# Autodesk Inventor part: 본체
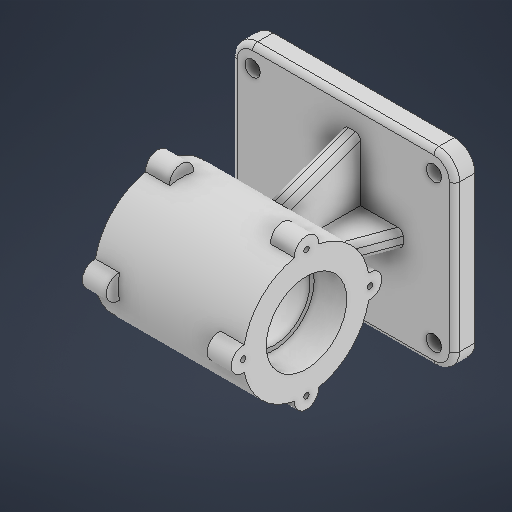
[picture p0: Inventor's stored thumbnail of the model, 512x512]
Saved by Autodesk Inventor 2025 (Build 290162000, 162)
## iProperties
Created: 2025-08
Part Number: 본체
Material: 일반
Document SubType Name: Modeling
Designer: infra11
Density: 1 g/cm^3
Appearance: 기본값
Author: infra11
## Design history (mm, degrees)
sketch "스케치1"
  geometry: L1 (-65, -55)-(65, -55); L2 (65, -55)-(65, 55); L3 (65, 55)-(-65, 55); L4 (-65, 55)-(-65, -55); L5 (-65, -55)-(65, 55); L6 (65, -55)-(-65, 55); 1 further point
  constraints: 12 end point, 2 midpoint, 2 parallel, 1 horizontal, 1 perpendicular
  dimensions: "d0" = 130 distance of L2.end L3.end; "d1" = 110 distance of L1.end L2.end
extrude "돌출1" new body sketch "스케치1" stored distance "d2" = 12; taper "d3" = 0 deg
sketch "스케치2"
  geometry: L1 (-53, -43)-(53, -43); L2 (53, -43)-(53, 43); L3 (53, 43)-(-53, 43); L4 (-53, 43)-(-53, -43); L5 (-53, -43)-(53, 43); L6 (53, -43)-(-53, 43); C1 r 4.5 at (-53, 43); C2 r 4.5 at (53, 43); C3 r 4.5 at (-53, -43); C4 r 4.5 at (53, -43); 1 further point
  constraints: 12 end point, 4 centre point, 4 coincident, 2 midpoint, 2 parallel, 1 horizontal, 1 perpendicular
  dimensions: "d4" = 106 distance of L2.end L3.end; "d5" = 86 distance of L1.end L2.end; "d6" = 9 diameter of C1; "d7" = 9 diameter of C3; "d8" = 9 diameter of C4; "d9" = 9 diameter of C2
extrude "돌출2" cut sketch "스케치2" extent not by distance; stored distance "d10" = 0; taper "d11" = 0 deg
sketch "스케치3"
  geometry: 1 further point
sketch "스케치4"
  geometry: L1 (38.5, 113)-(-48.5, 113); L2 (-48.5, 113)-(-48.5, 99.5); L3 (-48.5, 99.5)-(-29.5, 99.5); L4 (-29.5, 99.5)-(-29.5, 97); L5 (-29.5, 97)-(19.5, 97); L6 (19.5, 97)-(19.5, 99.5); L7 (19.5, 99.5)-(38.5, 99.5); L8 (38.5, 99.5)-(38.5, 113); L9 (-65, -6)-(65, -6) reference; L10 (38.5, 106.25)-(-5, 106.25); L11 (84.032, 76)-(-73.458, 76); 2 further points
  constraints: 20 end point, 6 perpendicular, 2 horizontal, 2 point on line, 1 midpoint, 1 parallel
  dimensions: "d12" = 2.5 distance of L4.end L3.end; "d13" = 2.5 distance of L5.end L6.end (derived); "d14" = 87 distance of L1.start L1.end; "d15" = 19 distance of L6.end L7.end; "d16" = 19 distance of L2.end L3.end; "d19" = 43.5 distance of L10.start L10.end; "d20" = 70 horizontal distance of point (65, 6) L10.end; "d22" = 21 distance between parallel lines of L11 L5 (derived); "d23" = 82 distance between parallel lines of L9 L11; "d24" = 23.5 distance between parallel lines of L11 L7; "d25" = 23.5 distance between parallel lines of L11 L3 (derived); "d26" = 37 distance between parallel lines of L11 L1
revolve "회전1" sketch "스케치4" stored, may be unused: angle "d27" = 90 deg
sketch "스케치5"
  geometry: L1 (-65, 6)-(65, 6); L2 (-35, 6)-(-22.989, 39); L3 (38.5, 39)-(-48.5, 39) reference; L4 (12.663, 39.895)-(25, 6); L5 (-65, 6)-(65, 6) reference; L6 (-35, 6)-(25, 6); L7 (-5, 6)-(-65, 6); L8 (12.989, 39)-(-22.989, 39); 2 further points
  constraints: 12 end point, 5 point on line, 3 collinear, 1 coincident, 1 midpoint
  dimensions: "d28" = 60 distance of L4.end L2.start; "d29" = 70 deg angle of L1 L2; "d30" = 70 deg angle of L1 L4; "d48" = 70 distance of L1.end point (-5, 6)
sketch "스케치6"
  geometry: C1 r 7 at (37, 0); C2 r 7 at (0, 37); C3 r 7 at (-37, 0); C4 r 7 at (0, -37); C5 r 23.5 at (0, 0) reference; A1 r 37 centre (0, 0) between (37, 0) and (0, 37); 4 further points
  constraints: 6 coincident, 5 centre point, 4 point on circle, 2 horizontal alignment, 2 vertical alignment
  dimensions: "d33" = 74 diameter of A1; "d34" = 14 diameter of C2; "d35" = 14 diameter of C1; "d36" = 14 diameter of C4; "d37" = 14 diameter of C3
extrude "돌출3" join sketch "스케치6" distance "d38" = 14; taper "d39" = 0 deg
sketch "스케치7" dims "d40" = 74
  geometry: L1 (-37, 44)-(-37, -37); L2 (7, 0)-(-81, 0); C1 r 23.5 at (-37, 0) reference; A1 r 7 centre (-37, 37) between (-30.031, 36.338) and (-43.969, 36.338) reference; A2 r 7 centre (-37, -37) between (-43.969, -36.338) and (-30.031, -36.338) reference; A3 r 37 centre (-37, 0) between (-43.969, 36.338) and (-30.031, 36.338) reference; A4 r 7 centre (0, 0) between (-0.662, -6.969) and (-0.662, 6.969) reference; A5 r 7 centre (-74, 0) between (-73.338, 6.969) and (-73.338, -6.969) reference; 2 further points
  constraints: 4 end point, 3 point on circle, 1 coincident, 1 horizontal, 1 vertical, 2 other
hole "구멍1" sketch "스케치7" at (0, 0), (-37, -37), (-37, 37), (-74, 0) diameter "d41" = 3.242; stored, may be unused: countersink angle "d45" = 90 deg, drill point angle "d47" = 118 deg; dims "d42" = 8, "d43" = 4, "d44" = 2, "d46" = 10
sketch "스케치8"
  geometry: 1 further point
extrude "돌출4" join sketch "스케치5" stored distance "d49" = 10; taper "d50" = 0 deg
sketch "스케치9"
  geometry: 1 further point
node "작업 평면1"
sketch "스케치10"
  geometry: L1 (-25.336, 49.036)-(-41, 6); L2 (-47.5, 6)-(-38.5, 6) reference; L3 (55, 6)-(-55, 6) reference; 2 further points
  constraints: 2 end point, 1 point on line, 2 other
  dimensions: "d52" = 70 deg angle of L3 L1; "d53" = 14 distance of L3.end L1.end
feature "리브1" sketch "스케치10" dims "d54" = 10, "d55" = 10, "d56" = 0, "d57" = 0, "d58" = 1, "d59" = 1
sketch "스케치11"
  geometry: C1 r 7 at (-37, 0); C2 r 7 at (0, -37); C3 r 7 at (0, 37); C4 r 7 at (37, 0); A1 r 37 centre (0, 0) between (-36.338, 6.969) and (-36.338, -6.969) reference; A2 r 7 centre (-37, 0) between (-36.338, 6.969) and (-36.338, -6.969) reference; 4 further points
  constraints: 4 centre point, 4 coincident
  dimensions: "d60" = 7 radius of A2 (derived); "d61" = 14 diameter of C2; "d62" = 14 diameter of C3; "d63" = 14 diameter of C4; "d74" = 14 diameter of C1
extrude "돌출5" join sketch "스케치11" distance "d64" = 14; taper "d65" = 0 deg
sketch "스케치12"
  geometry: A1 r 37 centre (-37, 0) between (-73.338, -6.969) and (-43.969, -36.338) reference; A2 r 7 centre (-74, 0) between (-73.338, 6.969) and (-73.338, -6.969) reference; A3 r 7 centre (-37, -37) between (-43.969, -36.338) and (-30.031, -36.338) reference; A4 r 7 centre (0, 0) between (-0.662, -6.969) and (-0.662, 6.969) reference; A5 r 7 centre (-37, 37) between (-30.031, 36.338) and (-43.969, 36.338) reference; 1 further point
hole "구멍2" sketch "스케치12" at (-74, 0), (-37, -37), (0, 0), (-37, 37) diameter "d66" = 3.242; stored, may be unused: countersink angle "d70" = 90 deg, drill point angle "d72" = 118 deg; dims "d67" = 8, "d68" = 4, "d69" = 2, "d71" = 10
fillet "모깎기1" dims "d73" = 12
fillet "모깎기2" dims "d75" = 3
fillet "모깎기3" dims "d76" = 3
fillet "모깎기4" dims "d77" = 3
node "솔리드1"
mirror "미러1"
feature "A9D066F2-1C7D-4E18-AEED-F7BC21143FA4" dims "d41" = 3.242, "d42" = 8, "d43" = 4, "d44" = 2, "d45" = 90 deg, "d46" = 10, "d47" = 118 deg
other parameters: "d51" = 5
